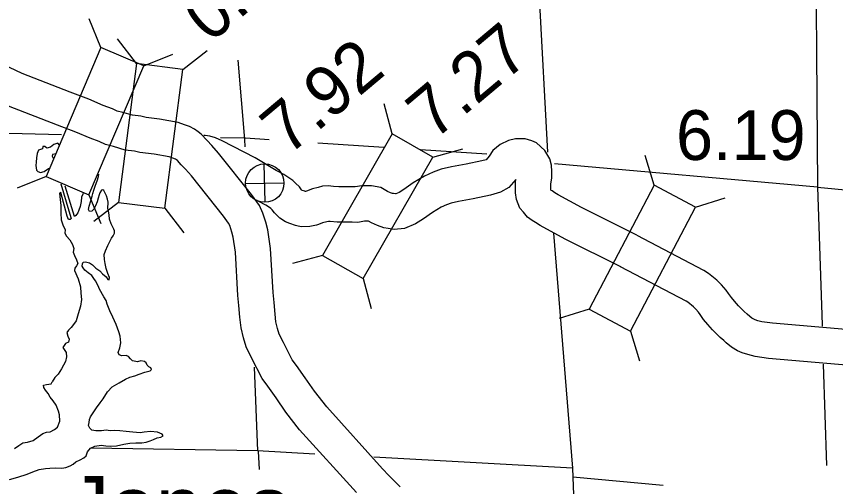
# Model space of a CAD drawing. Extents: x 369523 to 838377, y 495025 to 936819.
# Drawn here: x 630180 to 644076, y 896620 to 904597 of the extents above; entities that cross this region are included whole.
import ezdxf

# ---------------------------------------------------------------- set-up
doc = ezdxf.new("R2010")
doc.units = 0
for name, color, linetype in [('1', 7, 'Continuous'), ('DSN_BRDG_Annotation', 7, 'Continuous'), ('DSN_DRFT_Common-Annotations', 7, 'Continuous'), ('DSN_DRFT_Junk-No-Plot', 7, 'Continuous'), ('Level 1', 7, 'Continuous'), ('Level 10', 7, 'Continuous'), ('Level 11', 7, 'Continuous'), ('Level 15', 7, 'Continuous'), ('Level 21', 7, 'Continuous'), ('Level 22', 7, 'Continuous')]:
    doc.layers.add(name, color=color, linetype=linetype)

msp = doc.modelspace()

# ---------------------------------------------------------------- linework, layer by layer
at = {"layer": 'DSN_DRFT_Common-Annotations'}
for p, q in [((634400, 901443), (634385, 902094)), ((634067, 901761), (634718, 901776))]:
    msp.add_line(p, q, dxfattribs=at)
msp.add_circle((634393, 901769), 326, dxfattribs=at)
at = {"layer": 'Level 1'}
for points in [[(640702, 900884), (639767, 901353), (639368, 901568), (639315, 901601), (639266, 901635), (639252, 901645), (639244, 901654), (639244, 901748), (639260, 901857), (639263, 901967), (639254, 902072), (639226, 902180), (639145, 902320), (639002, 902451), (638926, 902483), (638811, 902522), (638725, 902519), (638646, 902517), (638528, 902492), (638388, 902422), (638261, 902320), (638201, 902227), (638147, 902166), (638076, 902145), (637810, 902089), (637561, 902043), (637387, 902006), (637247, 901955), (637100, 901887), (636912, 901771), (636754, 901662), (636671, 901609), (636618, 901587), (636608, 901586), (636579, 901590), (636561, 901593), (636527, 901605), (636474, 901629), (636360, 901694), (636202, 901723), (636127, 901721), (636038, 901721), (635925, 901704), (635882, 901704), (635783, 901705), (635647, 901705), (635559, 901713), (635470, 901721), (635373, 901714), (635301, 901693), (635201, 901672), (635099, 901632), (635085, 901629), (635078, 901629), (635071, 901631), (635029, 901644), (635026, 901645), (635023, 901647), (635017, 901653), (634982, 901704), (634917, 901768), (634870, 901812), (634801, 901858), (634714, 901915), (634588, 901980), (634228, 902198), (633670, 902487), (633555, 902535), (633464, 902563), (633380, 902575), (633360, 902576)], [(640433, 900348), (639490, 900820), (639062, 901051), (638983, 901102), (638931, 901137), (638848, 901193), (638781, 901273), (638718, 901344), (638663, 901489), (638644, 901602), (638644, 901793), (638649, 901828), (638531, 901696), (638392, 901613), (638224, 901563), (637926, 901500), (637678, 901455), (637553, 901428), (637476, 901400), (637386, 901358), (637239, 901268), (637087, 901163), (636950, 901075), (636763, 900998), (636589, 900981), (636489, 900997), (636415, 901008), (636304, 901048), (636203, 901092), (636153, 901121), (636135, 901121), (636083, 901121), (635970, 901103), (635877, 901104), (635780, 901105), (635620, 901105), (635504, 901115), (635474, 901118), (635447, 901110), (635371, 901094), (635306, 901069), (635268, 901055), (635159, 901031), (635009, 901027), (634939, 901045), (634916, 901050), (634817, 901081), (634744, 901114), (634648, 901174), (634556, 901265), (634520, 901317), (634499, 901338), (634496, 901340), (634472, 901356), (634412, 901395), (634295, 901456), (634251, 901482)], [(646279, 899111), (643003, 899392), (642827, 899416), (642757, 899434), (642709, 899450), (642678, 899464), (642656, 899476), (642621, 899507), (642577, 899548), (642524, 899592), (642476, 899640), (642430, 899687), (642362, 899764), (642309, 899826), (642259, 899897), (642218, 899950), (642143, 900044), (642059, 900120), (641921, 900236), (641841, 900285), (640707, 900881)], [(646236, 898512), (642938, 898796), (642712, 898826), (642585, 898859), (642492, 898891), (642410, 898926), (642310, 898983), (642218, 899061), (642180, 899098), (642119, 899147), (642047, 899220), (641990, 899279), (641910, 899370), (641835, 899457), (641777, 899540), (641748, 899577), (641703, 899632), (641664, 899669), (641569, 899748), (641543, 899764), (640427, 900350)]]:
    msp.add_lwpolyline(points, dxfattribs=at)
at = {"layer": 'Level 10'}
for points in [[(630919, 902408), (630885, 902444), (630818, 902421), (630759, 902376), (630699, 902362), (630664, 902388), (630628, 902389), (630621, 902351), (630587, 902340), (630558, 902327), (630531, 902269), (630520, 902196), (630518, 902124), (630513, 902066), (630521, 901988), (630547, 901966), (630588, 901951), (630651, 901965), (630724, 902018), (630751, 902023)], [(630795, 902256), (630786, 902224), (630809, 902180), (630813, 902180)], [(630853, 902267), (630795, 902256)], [(631694, 901589), (631665, 901641), (631649, 901656), (631625, 901648), (631596, 901605), (631585, 901567), (631570, 901513), (631550, 901452), (631523, 901385), (631496, 901329), (631459, 901292), (631419, 901289), (631402, 901323), (631413, 901379), (631441, 901470), (631465, 901546), (631477, 901591), (631495, 901651), (631523, 901736), (631548, 901807), (631572, 901881)], [(631572, 901881), (631580, 901920)], [(630936, 901759), (630977, 901603), (631068, 901300), (631111, 901167), (631095, 901151), (631067, 901152), (631044, 901208), (630937, 901610), (630909, 901599), (630924, 901490), (630934, 901388), (630937, 901257), (630941, 901145), (630971, 901058), (631005, 900978), (631004, 900922), (631029, 900867), (631086, 900806), (631132, 900729), (631154, 900659), (631141, 900598), (631164, 900539), (631200, 900468), (631221, 900406), (631202, 900365), (631169, 900327), (631167, 900288), (631229, 900144), (631266, 900008), (631276, 899902), (631284, 899794), (631266, 899683), (631229, 899550), (631192, 899431), (631149, 899372), (631110, 899319), (631067, 899274), (631036, 899232), (631051, 899174), (631077, 899122), (631064, 899068), (631014, 899047), (630968, 898982)], [(631309, 901579), (631285, 901531), (631280, 901455), (631260, 901372), (631241, 901312), (631224, 901266), (631191, 901219), (631166, 901202), (631010, 901718)], [(631472, 897854), (631538, 897956), (631602, 898042), (631652, 898109), (631724, 898227), (631804, 898312), (631921, 898379), (632029, 898441), (632107, 898475), (632192, 898497), (632261, 898529), (632359, 898559), (632450, 898583), (632470, 898607), (632463, 898635), (632427, 898652), (632400, 898682), (632383, 898720), (632351, 898745), (632293, 898752), (632235, 898738), (632151, 898755), (632114, 898786), (632083, 898829), (632043, 898842), (631969, 898841), (631922, 898854), (631905, 898898), (631936, 898974), (631952, 899061), (631942, 899171), (631918, 899245), (631873, 899372), (631815, 899493), (631768, 899602), (631720, 899715), (631701, 899775), (631665, 899842), (631592, 899971), (631565, 900028), (631523, 900110), (631496, 900151), (631459, 900199), (631398, 900245), (631339, 900290), (631311, 900330), (631294, 900361), (631299, 900398), (631313, 900426), (631352, 900433), (631421, 900414), (631472, 900381), (631529, 900324), (631594, 900280), (631641, 900232), (631702, 900178), (631729, 900134), (631755, 900129), (631758, 900167), (631733, 900234), (631701, 900318), (631687, 900404), (631676, 900472), (631672, 900558), (631694, 900620), (631731, 900709), (631767, 900780), (631796, 900837), (631821, 900876), (631842, 900922), (631847, 900960), (631831, 900988), (631787, 901079), (631759, 901159), (631753, 901233), (631740, 901291), (631729, 901338), (631735, 901443), (631728, 901495), (631710, 901550), (631694, 901589)], [(631311, 901592), (631309, 901579)], [(630968, 898982), (631025, 898897), (631031, 898821), (631015, 898742), (630947, 898619), (630889, 898527), (630833, 898470), (630789, 898396)], [(630648, 898300), (630639, 898342), (630691, 898355), (630771, 898366)], [(630771, 898366), (630789, 898396)], [(630146, 897267), (630223, 897315), (630290, 897364), (630368, 897374), (630467, 897400), (630552, 897466), (630627, 897524), (630690, 897543), (630756, 897551), (630827, 897590), (630875, 897631), (630920, 897730), (630912, 897836), (630893, 897902), (630853, 898003), (630807, 898073), (630754, 898140), (630722, 898201), (630677, 898256), (630648, 898300)], [(631146, 897002), (631191, 897039), (631265, 897075), (631326, 897108), (631363, 897143), (631388, 897211), (631438, 897271), (631510, 897306), (631617, 897323), (631696, 897310), (631770, 897308), (631878, 897314), (632003, 897341), (632105, 897359), (632207, 897363), (632311, 897363), (632380, 897375), (632448, 897398), (632505, 897420), (632569, 897447), (632633, 897458), (632670, 897481), (632653, 897511), (632575, 897543), (632456, 897553), (632349, 897541), (632279, 897533), (632153, 897546), (632044, 897554), (631936, 897566), (631844, 897572), (631772, 897568), (631704, 897575), (631624, 897567), (631528, 897565), (631460, 897576), (631429, 897611), (631406, 897655), (631415, 897709), (631422, 897761), (631439, 897802), (631472, 897854)], [(630062, 896742), (630203, 896783), (630366, 896831), (630461, 896871), (630566, 896911), (630674, 896926), (630750, 896933), (630851, 896941), (630950, 896932), (631017, 896943), (631093, 896975), (631146, 897002)]]:
    msp.add_lwpolyline(points, dxfattribs=at)
at = {"layer": 'Level 11'}
for points in [[(636692, 896616), (636498, 896809), (636393, 896924), (635444, 897972), (635236, 898237), (635076, 898468), (634932, 898675), (634859, 898772), (634709, 899063), (634638, 899209), (634610, 899300), (634583, 899416), (634567, 899548), (634554, 899746), (634535, 899912), (634492, 900662), (634444, 900974), (634411, 901105), (634360, 901260), (634305, 901390), (634169, 901574), (633610, 902274), (633497, 902404), (633414, 902494), (633315, 902597), (633261, 902639), (633199, 902685), (633115, 902728), (633033, 902757), (632925, 902795), (632607, 902853), (632383, 902881), (632289, 902903), (632148, 902920), (631986, 902968), (631891, 902991), (631813, 903028), (631651, 903087), (631410, 903190), (631094, 903309), (630280, 903628), (629958, 903778)], [(635949, 896519), (634985, 897585), (634753, 897881), (634584, 898125), (634445, 898323), (634348, 898453), (634172, 898794), (634078, 898989), (634031, 899143), (633991, 899311), (633969, 899493), (633956, 899692), (633937, 899861), (633895, 900599), (633855, 900854), (633834, 900938), (633798, 901049), (633781, 901089), (633693, 901208), (633149, 901891), (633051, 902003), (632978, 902081), (632912, 902150), (632897, 902162), (632881, 902174), (632877, 902176), (632833, 902192), (632772, 902213), (632515, 902260), (632277, 902290), (632186, 902311), (632027, 902330), (631829, 902388), (631691, 902423), (631583, 902473), (631430, 902529), (631186, 902633), (630879, 902749), (630044, 903076)]]:
    msp.add_lwpolyline(points, dxfattribs=at)
at = {"layer": 'Level 15'}
for points in [[(638711, 911502), (638907, 907652), (638908, 907544), (639187, 902295)], [(639293, 900919), (639612, 896933), (639620, 896783), (639678, 895144)]]:
    msp.add_lwpolyline(points, dxfattribs=at)
at = {"layer": 'Level 21'}
for p, q in [((631615, 904068), (631417, 904557)), ((632216, 903798), (631893, 904216)), ((632343, 903757), (632833, 903955)), ((633001, 903698), (633419, 904020)), ((636556, 902605), (636418, 903114)), ((637244, 902211), (637753, 902349)), ((640999, 901731), (640843, 902235)), ((630684, 901882), (630194, 901684)), ((631412, 901571), (631610, 901082)), ((631914, 901441), (631496, 901119)), ((641700, 901362), (642204, 901519)), ((632699, 901341), (633022, 900923)), ((635375, 900543), (634865, 900405)), ((636062, 900150), (636200, 899640)), ((639893, 899628), (639389, 899471)), ((640594, 899259), (640751, 898755))]:
    msp.add_line(p, q, dxfattribs=at)
for points in [[(631615, 904068), (630684, 901882), (631412, 901571), (632343, 903757)], [(632699, 901341), (633001, 903698), (632216, 903798), (631914, 901441)], [(636556, 902605), (635375, 900543), (636062, 900150), (637244, 902211)], [(640594, 899259), (641700, 901362), (640999, 901731), (639893, 899628)]]:
    msp.add_lwpolyline(points, close=True, dxfattribs=at)
at = {"layer": 'Level 22'}
for points in [[(643852, 899340), (643852, 899362), (643776, 901698), (643732, 907031), (643841, 912275)], [(633936, 903852), (634050, 902510), (634055, 902383)], [(630944, 902590), (628715, 902643)], [(634468, 902502), (634069, 902529), (633642, 902537)], [(636412, 902375), (635296, 902448)], [(638162, 902260), (637035, 902334)], [(643768, 901698), (639305, 902093)], [(643768, 901698), (646352, 901451), (649047, 901440), (654322, 901726)], [(634212, 898645), (634272, 897225)], [(643929, 896976), (643873, 898696)], [(635243, 897172), (634272, 897225), (631448, 897273)], [(634280, 897225), (634280, 897221), (634296, 896911)], [(639612, 896933), (636241, 897117)], [(641153, 896639), (639620, 896783)]]:
    msp.add_lwpolyline(points, dxfattribs=at)

# ---------------------------------------------------------------- texts
at = {"layer": '1'}
msp.add_text('Jones', height=1056, dxfattribs=at).set_placement((631053, 895747))
at = {"layer": 'DSN_BRDG_Annotation'}
msp.add_text('7.92', height=844.8, rotation=40, dxfattribs=at).set_placement((634785, 902216))
at = {"layer": 'DSN_DRFT_Junk-No-Plot'}
for s, p in [('0.74', (633463, 904126)), ('7.27', (637261, 902479)), ('7.92', (634785, 902216))]:
    msp.add_text(s, height=844.8, rotation=40, dxfattribs=at).set_placement(p)
msp.add_text('6.19', height=844.8, dxfattribs=at).set_placement((641369, 902161))

doc.saveas('drawing.dxf')
